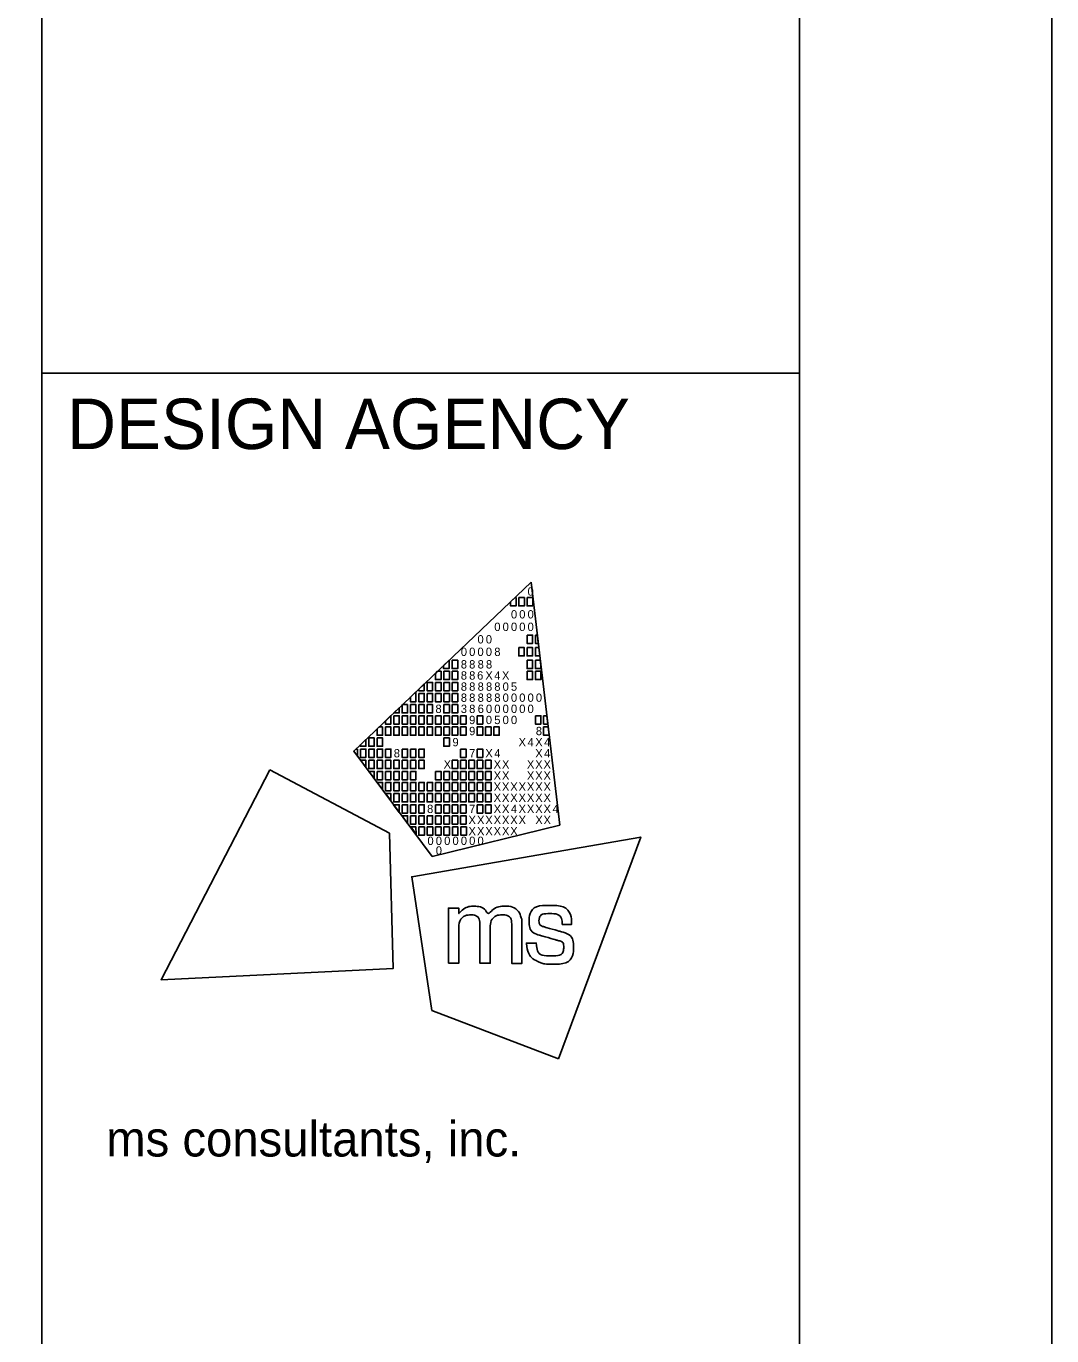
# Model space of a CAD drawing. Extents: x 0 to 34, y -1.2 to 22.
# Drawn here: x 31.969 to 34, y 2.594 to 5.188 of the extents above; entities that cross this region are included whole.
import ezdxf

# ---------------------------------------------------------------- set-up
doc = ezdxf.new("R2010")
doc.units = 0
for name, color, linetype in [('SH_Border', 7, 'Continuous'), ('SH_Cut_Line', 7, 'Continuous'), ('SH_Data', 7, 'Continuous')]:
    doc.layers.add(name, color=color, linetype=linetype)

msp = doc.modelspace()

# ---------------------------------------------------------------- linework, layer by layer
at = {"layer": 'SH_Border'}
for p, q in [((32, 0.5), (32, 21.5)), ((32, 4.5), (33.5, 4.5))]:
    msp.add_line(p, q, dxfattribs=at)
msp.add_lwpolyline([(1.5, 21.5), (33.5, 21.5), (33.5, 0.5), (1.5, 0.5)], close=True, dxfattribs=at)
at = {"layer": 'SH_Cut_Line'}
for p, q in [((32.6175, 3.7519), (32.9688, 4.0861)), ((32.9688, 4.0861), (32.9688, 4.0861)), ((32.9688, 4.0861), (33.0253, 3.6052)), ((32.773, 3.543), (32.6175, 3.7519)), ((33.0253, 3.6052), (32.773, 3.543))]:
    msp.add_line(p, q, dxfattribs=at)
for points in [[(0, 0), (34, 0), (34, 22), (0, 22)], [(32.9279, 4.0472), (32.9369, 4.0558), (32.9389, 4.0558), (32.9389, 4.0393), (32.9279, 4.0393)], [(32.9444, 4.0558), (32.9554, 4.0558), (32.9554, 4.0393), (32.9444, 4.0393)], [(32.9609, 4.0558), (32.9719, 4.0558), (32.9719, 4.0393), (32.9609, 4.0393)], [(32.9606, 3.9815), (32.9716, 3.9815), (32.9716, 3.965), (32.9606, 3.965)], [(32.9771, 3.9815), (32.9811, 3.9815), (32.983, 3.965), (32.9771, 3.965)], [(32.9441, 3.9567), (32.9551, 3.9567), (32.9551, 3.9402), (32.9441, 3.9402)], [(32.9606, 3.9567), (32.9716, 3.9567), (32.9716, 3.9402), (32.9606, 3.9402)], [(32.9771, 3.9567), (32.984, 3.9567), (32.9859, 3.9402), (32.9771, 3.9402)], [(32.7953, 3.9211), (32.8064, 3.9316), (32.8064, 3.9154), (32.7953, 3.9154)], [(32.8123, 3.9319), (32.8233, 3.9319), (32.8233, 3.9154), (32.8123, 3.9154)], [(32.9606, 3.9319), (32.9716, 3.9319), (32.9716, 3.9154), (32.9606, 3.9154)], [(32.9771, 3.9319), (32.9869, 3.9319), (32.9881, 3.9218), (32.9881, 3.9154), (32.9771, 3.9154)], [(32.7958, 3.9099), (32.8068, 3.9099), (32.8068, 3.8934), (32.7958, 3.8934)], [(32.8123, 3.9099), (32.8233, 3.9099), (32.8233, 3.8934), (32.8123, 3.8934)], [(32.9606, 3.9099), (32.9716, 3.9099), (32.9716, 3.8934), (32.9606, 3.8934)], [(32.9771, 3.9099), (32.9881, 3.9099), (32.9881, 3.8934), (32.9771, 3.8934)], [(32.7462, 3.8659), (32.7572, 3.8659), (32.7572, 3.8494), (32.7462, 3.8494)], [(32.7627, 3.8879), (32.7737, 3.8879), (32.7737, 3.8714), (32.7627, 3.8714)], [(32.7627, 3.8659), (32.7737, 3.8659), (32.7737, 3.8494), (32.7627, 3.8494)], [(32.7793, 3.8879), (32.7903, 3.8879), (32.7903, 3.8714), (32.7793, 3.8714)], [(32.7793, 3.8659), (32.7903, 3.8659), (32.7903, 3.8494), (32.7793, 3.8494)], [(32.7958, 3.8879), (32.8068, 3.8879), (32.8068, 3.8714), (32.7958, 3.8714)], [(32.7958, 3.8659), (32.8068, 3.8659), (32.8068, 3.8494), (32.7958, 3.8494)], [(32.8123, 3.8879), (32.8233, 3.8879), (32.8233, 3.8714), (32.8123, 3.8714)], [(32.8123, 3.8659), (32.8233, 3.8659), (32.8233, 3.8494), (32.8123, 3.8494)], [(32.7297, 3.8439), (32.7407, 3.8439), (32.7407, 3.8273), (32.7297, 3.8273)], [(32.7462, 3.8439), (32.7572, 3.8439), (32.7572, 3.8273), (32.7462, 3.8273)], [(32.7627, 3.8439), (32.7737, 3.8439), (32.7737, 3.8273), (32.7627, 3.8273)], [(32.7958, 3.8439), (32.8068, 3.8439), (32.8068, 3.8273), (32.7958, 3.8273)], [(32.8123, 3.8439), (32.8233, 3.8439), (32.8233, 3.8273), (32.8123, 3.8273)], [(32.6967, 3.8218), (32.7077, 3.8218), (32.7077, 3.8053), (32.6967, 3.8053)], [(32.7132, 3.8218), (32.7242, 3.8218), (32.7242, 3.8053), (32.7132, 3.8053)], [(32.7297, 3.8218), (32.7407, 3.8218), (32.7407, 3.8053), (32.7297, 3.8053)], [(32.7462, 3.8218), (32.7572, 3.8218), (32.7572, 3.8053), (32.7462, 3.8053)], [(32.7627, 3.8218), (32.7737, 3.8218), (32.7737, 3.8053), (32.7627, 3.8053)], [(32.7793, 3.8218), (32.7903, 3.8218), (32.7903, 3.8053), (32.7793, 3.8053)], [(32.7958, 3.8218), (32.8068, 3.8218), (32.8068, 3.8053), (32.7958, 3.8053)], [(32.8123, 3.8218), (32.8233, 3.8218), (32.8233, 3.8053), (32.8123, 3.8053)], [(32.8288, 3.8218), (32.8398, 3.8218), (32.8398, 3.8053), (32.8288, 3.8053)], [(32.8618, 3.8218), (32.8728, 3.8218), (32.8728, 3.8053), (32.8618, 3.8053)], [(32.9771, 3.8218), (32.9881, 3.8218), (32.9881, 3.8053), (32.9771, 3.8053)], [(32.9935, 3.8218), (32.9998, 3.8218), (33.0018, 3.8053), (32.9935, 3.8053)], [(32.6802, 3.7998), (32.6912, 3.7998), (32.6912, 3.7833), (32.6802, 3.7833)], [(32.6967, 3.7998), (32.7077, 3.7998), (32.7077, 3.7833), (32.6967, 3.7833)], [(32.7132, 3.7998), (32.7242, 3.7998), (32.7242, 3.7833), (32.7132, 3.7833)], [(32.7297, 3.7998), (32.7407, 3.7998), (32.7407, 3.7833), (32.7297, 3.7833)], [(32.7462, 3.7998), (32.7572, 3.7998), (32.7572, 3.7833), (32.7462, 3.7833)], [(32.7627, 3.7998), (32.7737, 3.7998), (32.7737, 3.7833), (32.7627, 3.7833)], [(32.7793, 3.7998), (32.7903, 3.7998), (32.7903, 3.7833), (32.7793, 3.7833)], [(32.7958, 3.7998), (32.8068, 3.7998), (32.8068, 3.7833), (32.7958, 3.7833)], [(32.8123, 3.7998), (32.8233, 3.7998), (32.8233, 3.7833), (32.8123, 3.7833)], [(32.8288, 3.7998), (32.8398, 3.7998), (32.8398, 3.7833), (32.8288, 3.7833)], [(32.8618, 3.7998), (32.8728, 3.7998), (32.8728, 3.7833), (32.8618, 3.7833)], [(32.8783, 3.7998), (32.8893, 3.7998), (32.8893, 3.7833), (32.8783, 3.7833)], [(32.8947, 3.7998), (32.9057, 3.7998), (32.9057, 3.7833), (32.8947, 3.7833)], [(32.9935, 3.7998), (33.0024, 3.7998), (33.0044, 3.7833), (32.9935, 3.7833)], [(32.6471, 3.7778), (32.6581, 3.7778), (32.6581, 3.7613), (32.6471, 3.7613)], [(32.6637, 3.7778), (32.6747, 3.7778), (32.6747, 3.7613), (32.6637, 3.7613)], [(32.7958, 3.7778), (32.8068, 3.7778), (32.8068, 3.7613), (32.7958, 3.7613)], [(32.6306, 3.7558), (32.6416, 3.7558), (32.6416, 3.7393), (32.6306, 3.7393)], [(32.6471, 3.7558), (32.6581, 3.7558), (32.6581, 3.7393), (32.6471, 3.7393)], [(32.6637, 3.7558), (32.6747, 3.7558), (32.6747, 3.7393), (32.6637, 3.7393)], [(32.6802, 3.7558), (32.6912, 3.7558), (32.6912, 3.7393), (32.6802, 3.7393)], [(32.7132, 3.7558), (32.7242, 3.7558), (32.7242, 3.7393), (32.7132, 3.7393)], [(32.7297, 3.7558), (32.7407, 3.7558), (32.7407, 3.7393), (32.7297, 3.7393)], [(32.7462, 3.7558), (32.7572, 3.7558), (32.7572, 3.7393), (32.7462, 3.7393)], [(32.8288, 3.7558), (32.8398, 3.7558), (32.8398, 3.7393), (32.8288, 3.7393)], [(32.8618, 3.7558), (32.8728, 3.7558), (32.8728, 3.7393), (32.8618, 3.7393)], [(32.6306, 3.7338), (32.6416, 3.7338), (32.6416, 3.72)], [(32.6471, 3.7338), (32.6581, 3.7338), (32.6581, 3.7173), (32.6471, 3.7173)], [(32.6471, 3.7117), (32.6581, 3.7117), (32.6581, 3.698)], [(32.6637, 3.7338), (32.6747, 3.7338), (32.6747, 3.7173), (32.6637, 3.7173)], [(32.6637, 3.7117), (32.6747, 3.7117), (32.6747, 3.6952), (32.6637, 3.6952)], [(32.6802, 3.7338), (32.6912, 3.7338), (32.6912, 3.7173), (32.6802, 3.7173)], [(32.6802, 3.7117), (32.6912, 3.7117), (32.6912, 3.6952), (32.6802, 3.6952)], [(32.6967, 3.7338), (32.7077, 3.7338), (32.7077, 3.7173), (32.6967, 3.7173)], [(32.6967, 3.7117), (32.7077, 3.7117), (32.7077, 3.6952), (32.6967, 3.6952)], [(32.7132, 3.7338), (32.7242, 3.7338), (32.7242, 3.7173), (32.7132, 3.7173)], [(32.7132, 3.7117), (32.7242, 3.7117), (32.7242, 3.6952), (32.7132, 3.6952)], [(32.7297, 3.7338), (32.7407, 3.7338), (32.7407, 3.7173), (32.7297, 3.7173)], [(32.7297, 3.7117), (32.7407, 3.7117), (32.7407, 3.6952), (32.7297, 3.6952)], [(32.7462, 3.7338), (32.7572, 3.7338), (32.7572, 3.7173), (32.7462, 3.7173)], [(32.7793, 3.7117), (32.7903, 3.7117), (32.7903, 3.6952), (32.7793, 3.6952)], [(32.7958, 3.7117), (32.8068, 3.7117), (32.8068, 3.6952), (32.7958, 3.6952)], [(32.8123, 3.7338), (32.8233, 3.7338), (32.8233, 3.7173), (32.8123, 3.7173)], [(32.8123, 3.7117), (32.8233, 3.7117), (32.8233, 3.6952), (32.8123, 3.6952)], [(32.8288, 3.7338), (32.8398, 3.7338), (32.8398, 3.7173), (32.8288, 3.7173)], [(32.8288, 3.7117), (32.8398, 3.7117), (32.8398, 3.6952), (32.8288, 3.6952)], [(32.8453, 3.7338), (32.8563, 3.7338), (32.8563, 3.7173), (32.8453, 3.7173)], [(32.8453, 3.7117), (32.8563, 3.7117), (32.8563, 3.6952), (32.8453, 3.6952)], [(32.8618, 3.7338), (32.8728, 3.7338), (32.8728, 3.7173), (32.8618, 3.7173)], [(32.8618, 3.7117), (32.8728, 3.7117), (32.8728, 3.6952), (32.8618, 3.6952)], [(32.8783, 3.7338), (32.8893, 3.7338), (32.8893, 3.7173), (32.8783, 3.7173)], [(32.8783, 3.7117), (32.8893, 3.7117), (32.8893, 3.6952), (32.8783, 3.6952)], [(32.6637, 3.6897), (32.6747, 3.6897), (32.6747, 3.676)], [(32.6747, 3.6897), (32.6747, 3.6897), (32.6747, 3.6897)], [(32.6802, 3.6897), (32.6912, 3.6897), (32.6912, 3.6732), (32.6802, 3.6732)], [(32.6967, 3.6897), (32.7077, 3.6897), (32.7077, 3.6732), (32.6967, 3.6732)], [(32.7132, 3.6897), (32.7242, 3.6897), (32.7242, 3.6732), (32.7132, 3.6732)], [(32.7297, 3.6897), (32.7407, 3.6897), (32.7407, 3.6732), (32.7297, 3.6732)], [(32.7462, 3.6897), (32.7572, 3.6897), (32.7572, 3.6732), (32.7462, 3.6732)], [(32.7627, 3.6897), (32.7737, 3.6897), (32.7737, 3.6732), (32.7627, 3.6732)], [(32.7793, 3.6897), (32.7903, 3.6897), (32.7903, 3.6732), (32.7793, 3.6732)], [(32.7958, 3.6897), (32.8068, 3.6897), (32.8068, 3.6732), (32.7958, 3.6732)], [(32.8123, 3.6897), (32.8233, 3.6897), (32.8233, 3.6732), (32.8123, 3.6732)], [(32.8288, 3.6897), (32.8398, 3.6897), (32.8398, 3.6732), (32.8288, 3.6732)], [(32.8453, 3.6897), (32.8563, 3.6897), (32.8563, 3.6732), (32.8453, 3.6732)], [(32.8618, 3.6897), (32.8728, 3.6897), (32.8728, 3.6732), (32.8618, 3.6732)], [(32.8783, 3.6897), (32.8893, 3.6897), (32.8893, 3.6732), (32.8783, 3.6732)], [(32.6802, 3.6677), (32.6912, 3.6677), (32.6912, 3.654)], [(32.6967, 3.6677), (32.7077, 3.6677), (32.7077, 3.6512), (32.6967, 3.6512)], [(32.7132, 3.6677), (32.7242, 3.6677), (32.7242, 3.6512), (32.7132, 3.6512)], [(32.7297, 3.6677), (32.7407, 3.6677), (32.7407, 3.6512), (32.7297, 3.6512)], [(32.7462, 3.6677), (32.7572, 3.6677), (32.7572, 3.6512), (32.7462, 3.6512)], [(32.7627, 3.6677), (32.7737, 3.6677), (32.7737, 3.6512), (32.7627, 3.6512)], [(32.7793, 3.6677), (32.7903, 3.6677), (32.7903, 3.6512), (32.7793, 3.6512)], [(32.7958, 3.6677), (32.8068, 3.6677), (32.8068, 3.6512), (32.7958, 3.6512)], [(32.8123, 3.6677), (32.8233, 3.6677), (32.8233, 3.6512), (32.8123, 3.6512)], [(32.8288, 3.6677), (32.8398, 3.6677), (32.8398, 3.6512), (32.8288, 3.6512)], [(32.8453, 3.6677), (32.8563, 3.6677), (32.8563, 3.6512), (32.8453, 3.6512)], [(32.8618, 3.6677), (32.8728, 3.6677), (32.8728, 3.6512), (32.8618, 3.6512)], [(32.8783, 3.6677), (32.8893, 3.6677), (32.8893, 3.6512), (32.8783, 3.6512)], [(32.7077, 3.6305), (32.6965, 3.6457), (32.7077, 3.6457)], [(32.7132, 3.6457), (32.7242, 3.6457), (32.7242, 3.6292), (32.7132, 3.6292)], [(32.7297, 3.6457), (32.7407, 3.6457), (32.7407, 3.6292), (32.7297, 3.6292)], [(32.7462, 3.6457), (32.7572, 3.6457), (32.7572, 3.6292), (32.7462, 3.6292)], [(32.7793, 3.6457), (32.7903, 3.6457), (32.7903, 3.6292), (32.7793, 3.6292)], [(32.7958, 3.6457), (32.8068, 3.6457), (32.8068, 3.6292), (32.7958, 3.6292)], [(32.8123, 3.6457), (32.8233, 3.6457), (32.8233, 3.6292), (32.8123, 3.6292)], [(32.8288, 3.6457), (32.8398, 3.6457), (32.8398, 3.6292), (32.8288, 3.6292)], [(32.8618, 3.6457), (32.8728, 3.6457), (32.8728, 3.6292), (32.8618, 3.6292)], [(32.8783, 3.6457), (32.8893, 3.6457), (32.8893, 3.6292), (32.8783, 3.6292)], [(32.724, 3.6082), (32.7132, 3.6237), (32.7242, 3.6237)], [(32.7297, 3.6237), (32.7407, 3.6237), (32.7407, 3.6072), (32.7297, 3.6072)], [(32.7462, 3.6237), (32.7572, 3.6237), (32.7572, 3.6072), (32.7462, 3.6072)], [(32.7627, 3.6237), (32.7737, 3.6237), (32.7737, 3.6072), (32.7627, 3.6072)], [(32.7793, 3.6237), (32.7903, 3.6237), (32.7903, 3.6072), (32.7793, 3.6072)], [(32.7958, 3.6237), (32.8068, 3.6237), (32.8068, 3.6072), (32.7958, 3.6072)], [(32.8123, 3.6237), (32.8233, 3.6237), (32.8233, 3.6072), (32.8123, 3.6072)], [(32.8288, 3.6237), (32.8398, 3.6237), (32.8398, 3.6072), (32.8288, 3.6072)], [(32.7302, 3.6017), (32.7407, 3.6017), (32.7408, 3.5875)], [(32.7463, 3.6017), (32.7573, 3.6017), (32.7573, 3.5852), (32.7463, 3.5852)], [(32.763, 3.6017), (32.774, 3.6017), (32.774, 3.5852), (32.763, 3.5852)], [(32.7794, 3.6017), (32.7904, 3.6017), (32.7904, 3.5852), (32.7794, 3.5852)], [(32.796, 3.6017), (32.807, 3.6017), (32.807, 3.5852), (32.796, 3.5852)], [(32.8129, 3.6017), (32.8239, 3.6017), (32.8239, 3.5851), (32.8129, 3.5851)], [(32.8296, 3.6017), (32.8406, 3.6017), (32.8406, 3.5851), (32.8296, 3.5851)]]:
    msp.add_lwpolyline(points, close=True, dxfattribs=at)
for points in [[(32.7903, 3.9099), (32.7836, 3.9099), (32.7793, 3.9058), (32.7793, 3.8934), (32.7903, 3.8934), (32.7903, 3.9099)], [(32.7407, 3.8691), (32.7297, 3.8587), (32.7297, 3.8494), (32.7407, 3.8494), (32.7407, 3.8691)], [(32.7572, 3.8849), (32.7462, 3.8744), (32.7462, 3.8714), (32.7572, 3.8714), (32.7572, 3.8849)], [(32.7242, 3.8439), (32.7141, 3.8439), (32.7132, 3.843), (32.7132, 3.8273), (32.7242, 3.8273), (32.7242, 3.8439)], [(32.6912, 3.822), (32.6802, 3.8115), (32.6802, 3.8053), (32.6912, 3.8053), (32.6912, 3.822)], [(32.7077, 3.8377), (32.6968, 3.8273), (32.7077, 3.8273), (32.7077, 3.8377)], [(32.6747, 3.7998), (32.6679, 3.7998), (32.6637, 3.7958), (32.6637, 3.7833), (32.6747, 3.7833), (32.6747, 3.7998)], [(32.6416, 3.7749), (32.6306, 3.7644), (32.6306, 3.7613), (32.6416, 3.7613), (32.6416, 3.7749)], [(32.6251, 3.7558), (32.6216, 3.7558), (32.6175, 3.7519), (32.6251, 3.7417), (32.6251, 3.7558)], [(32.4512, 3.7149), (32.2359, 3.2988), (32.6956, 3.3215), (32.6884, 3.5892), (32.4512, 3.7149)], [(33.0229, 3.1422), (33.1859, 3.5814), (32.7324, 3.5029), (32.7722, 3.2381), (33.0229, 3.1422)]]:
    msp.add_lwpolyline(points, dxfattribs=at)
for points in [[(32.8048, 3.3315), (32.8048, 3.3315), (32.8048, 3.4409), (32.8048, 3.4409), (32.8048, 3.4409), (32.8255, 3.4409), (32.8255, 3.4409), (32.8255, 3.4409), (32.8255, 3.4297), (32.8255, 3.4297), (32.8346, 3.4399), (32.8457, 3.4445), (32.8555, 3.4445), (32.8688, 3.4445), (32.8791, 3.4372), (32.8837, 3.4266), (32.8915, 3.4381), (32.905, 3.4446), (32.9166, 3.4446), (32.9325, 3.4446), (32.9451, 3.435), (32.9494, 3.4213), (32.9494, 3.4212), (32.9494, 3.4212), (32.9494, 3.4212), (32.9501, 3.419), (32.9506, 3.4172), (32.9506, 3.4071), (32.9506, 3.4071), (32.9506, 3.3314), (32.9506, 3.3314), (32.9506, 3.3314), (32.9303, 3.3314), (32.9303, 3.3314), (32.9303, 3.3314), (32.9303, 3.4048), (32.9303, 3.4048), (32.9303, 3.4201), (32.9219, 3.4274), (32.911, 3.4274), (32.8995, 3.4274), (32.8879, 3.4171), (32.8879, 3.4001), (32.8879, 3.4001), (32.8879, 3.3315), (32.8879, 3.3315), (32.8879, 3.3315), (32.8674, 3.3315), (32.8674, 3.3315), (32.8674, 3.3315), (32.8674, 3.4059), (32.8674, 3.4059), (32.8674, 3.4203), (32.8588, 3.4274), (32.8496, 3.4274), (32.8384, 3.4274), (32.8254, 3.417), (32.8254, 3.3962), (32.8254, 3.3962), (32.8254, 3.3315), (32.8254, 3.3315), (32.8254, 3.3315), (32.8048, 3.3315), (32.8048, 3.3315)], [(32.9595, 3.3709), (32.9595, 3.3709), (32.9595, 3.3717), (32.9595, 3.3717), (32.9595, 3.3717), (32.9603, 3.3717), (32.9603, 3.3717), (32.9603, 3.3717), (32.9783, 3.3717), (32.9783, 3.3717), (32.9783, 3.3717), (32.9789, 3.3717), (32.9789, 3.3717), (32.9789, 3.3717), (32.979, 3.371), (32.979, 3.371), (32.9803, 3.3554), (32.9887, 3.346), (33.009, 3.346), (33.0273, 3.346), (33.0333, 3.3554), (33.0333, 3.3631), (33.0333, 3.3732), (33.0256, 3.3758), (33.0175, 3.378), (33.0175, 3.378), (32.987, 3.3867), (32.987, 3.3867), (32.972, 3.3909), (32.9648, 3.4019), (32.9648, 3.4142), (32.9648, 3.4303), (32.9768, 3.4462), (33.0052, 3.4462), (33.0348, 3.4462), (33.0489, 3.4285), (33.0489, 3.4095), (33.0489, 3.4095), (33.0489, 3.4087), (33.0489, 3.4087), (33.0489, 3.4087), (33.0482, 3.4087), (33.0482, 3.4087), (33.0482, 3.4087), (33.0312, 3.4087), (33.0312, 3.4087), (33.0312, 3.4087), (33.0305, 3.4087), (33.0305, 3.4087), (33.0305, 3.4087), (33.0305, 3.4094), (33.0305, 3.4094), (33.0301, 3.4208), (33.0226, 3.43), (33.0056, 3.43), (32.9891, 3.43), (32.9843, 3.4218), (32.9843, 3.4157), (32.9843, 3.4108), (32.9869, 3.4059), (32.9959, 3.4033), (32.9959, 3.4033), (33.0255, 3.3948), (33.0255, 3.3948), (33.0462, 3.3889), (33.0527, 3.3777), (33.0527, 3.3639), (33.0527, 3.3462), (33.041, 3.3298), (33.0087, 3.3298), (32.9952, 3.3298), (32.9877, 3.3321), (32.9823, 3.3348), (32.969, 3.3414), (32.9609, 3.3536), (32.9595, 3.3709)]]:
    msp.add_open_spline(points, degree=3, dxfattribs=at)
at = {"layer": 'SH_Data'}
msp.add_line((32.75, 3.5), (32.75, 3.5), dxfattribs=at)

# ---------------------------------------------------------------- texts
at = {"layer": 'SH_Border'}
msp.add_text('ms consultants, inc.', height=0.07, rotation=360, dxfattribs=at).set_placement((32.1273, 2.9489))
at = {"layer": 'SH_Cut_Line'}
for s, p in [('0', (32.9617, 4.0597)), ('0', (32.9288, 4.0145)), ('0', (32.9452, 4.0145)), ('0', (32.9617, 4.0145)), ('0', (32.8958, 3.9897)), ('0', (32.9123, 3.9897)), ('0', (32.9288, 3.9897)), ('0', (32.9452, 3.9897)), ('0', (32.9617, 3.9897)), ('0', (32.8625, 3.965)), ('0', (32.879, 3.965)), ('0', (32.8295, 3.9402)), ('0', (32.846, 3.9402)), ('0', (32.8625, 3.9402)), ('0', (32.879, 3.9402)), ('8', (32.8958, 3.9402)), ('8', (32.8295, 3.9154)), ('8', (32.846, 3.9154)), ('8', (32.8628, 3.9154)), ('8', (32.8793, 3.9154)), ('8', (32.8295, 3.8934)), ('8', (32.846, 3.8934)), ('6', (32.8618, 3.8934)), ('X', (32.8781, 3.8934)), ('4', (32.8958, 3.8934)), ('X', (32.911, 3.8934)), ('8', (32.8295, 3.8713)), ('8', (32.8295, 3.8494)), ('8', (32.846, 3.8713)), ('8', (32.846, 3.8494)), ('8', (32.8628, 3.8713)), ('8', (32.8628, 3.8494)), ('8', (32.8794, 3.8713)), ('8', (32.8794, 3.8494)), ('8', (32.8958, 3.8713)), ('8', (32.8958, 3.8494)), ('0', (32.9123, 3.8713)), ('0', (32.9123, 3.8494)), ('5', (32.9287, 3.8713)), ('0', (32.9288, 3.8494)), ('0', (32.9452, 3.8494)), ('0', (32.9617, 3.8494)), ('0', (32.9782, 3.8494)), ('8', (32.7793, 3.8273)), ('3', (32.8295, 3.8273)), ('8', (32.846, 3.8273)), ('6', (32.8629, 3.8273)), ('0', (32.8793, 3.8273)), ('0', (32.8958, 3.8273)), ('0', (32.9123, 3.8273)), ('0', (32.9288, 3.8273)), ('0', (32.9452, 3.8273)), ('0', (32.9617, 3.8273)), ('9', (32.846, 3.8053)), ('0', (32.879, 3.8053)), ('5', (32.8957, 3.8053)), ('0', (32.9123, 3.8053)), ('0', (32.9288, 3.8053)), ('9', (32.846, 3.7833)), ('8', (32.9781, 3.7833)), ('9', (32.813, 3.7613)), ('X', (32.9439, 3.7613)), ('4', (32.9617, 3.7613)), ('X', (32.9769, 3.7613)), ('4', (32.9946, 3.7613)), ('8', (32.6967, 3.7393)), ('7', (32.846, 3.7393)), ('X', (32.8781, 3.7393)), ('4', (32.8958, 3.7393)), ('X', (32.9769, 3.7393)), ('4', (32.9946, 3.7393)), ('X', (32.7955, 3.7173)), ('X', (32.8945, 3.7173)), ('X', (32.8945, 3.6952)), ('X', (32.911, 3.7173)), ('X', (32.911, 3.6952)), ('X', (32.9604, 3.7173)), ('X', (32.9604, 3.6952)), ('X', (32.9769, 3.7173)), ('X', (32.9769, 3.6952)), ('X', (32.9933, 3.7173)), ('X', (32.9933, 3.6952)), ('X', (32.8945, 3.6732)), ('X', (32.911, 3.6732)), ('X', (32.9274, 3.6732)), ('X', (32.9439, 3.6732)), ('X', (32.9604, 3.6732)), ('X', (32.9769, 3.6732)), ('X', (32.9933, 3.6732)), ('X', (32.8945, 3.6512)), ('X', (32.911, 3.6512)), ('X', (32.9274, 3.6512)), ('X', (32.9439, 3.6512)), ('X', (32.9604, 3.6512)), ('X', (32.9769, 3.6512)), ('X', (32.9933, 3.6512)), ('8', (32.7627, 3.6292)), ('7', (32.846, 3.6292)), ('X', (32.8945, 3.6292)), ('X', (32.911, 3.6292)), ('4', (32.9288, 3.6292)), ('X', (32.9439, 3.6292)), ('X', (32.9604, 3.6292)), ('X', (32.9769, 3.6292)), ('X', (32.9933, 3.6292)), ('4', (33.0111, 3.6292)), ('X', (32.8447, 3.6072)), ('X', (32.8616, 3.6072)), ('X', (32.878, 3.6072)), ('X', (32.8945, 3.6072)), ('X', (32.911, 3.6072)), ('X', (32.9274, 3.6072)), ('X', (32.9439, 3.6072)), ('X', (32.9771, 3.6072)), ('X', (32.9933, 3.6072)), ('0', (32.7634, 3.5659)), ('0', (32.7799, 3.5659)), ('0', (32.7965, 3.5659)), ('0', (32.813, 3.5659)), ('0', (32.8295, 3.5659)), ('X', (32.8447, 3.5851)), ('0', (32.846, 3.5659)), ('X', (32.8616, 3.5851)), ('0', (32.8625, 3.5659)), ('X', (32.878, 3.5851)), ('X', (32.8945, 3.5851)), ('X', (32.911, 3.5851)), ('X', (32.9274, 3.5851)), ('0', (32.7799, 3.5467))]:
    msp.add_text(s, height=0.0165, rotation=360, dxfattribs=at).set_placement(p)
at = {"layer": 'SH_Data'}
msp.add_text('DESIGN AGENCY', height=0.1, dxfattribs=at).set_placement((32.05, 4.35))

doc.saveas('drawing.dxf')
